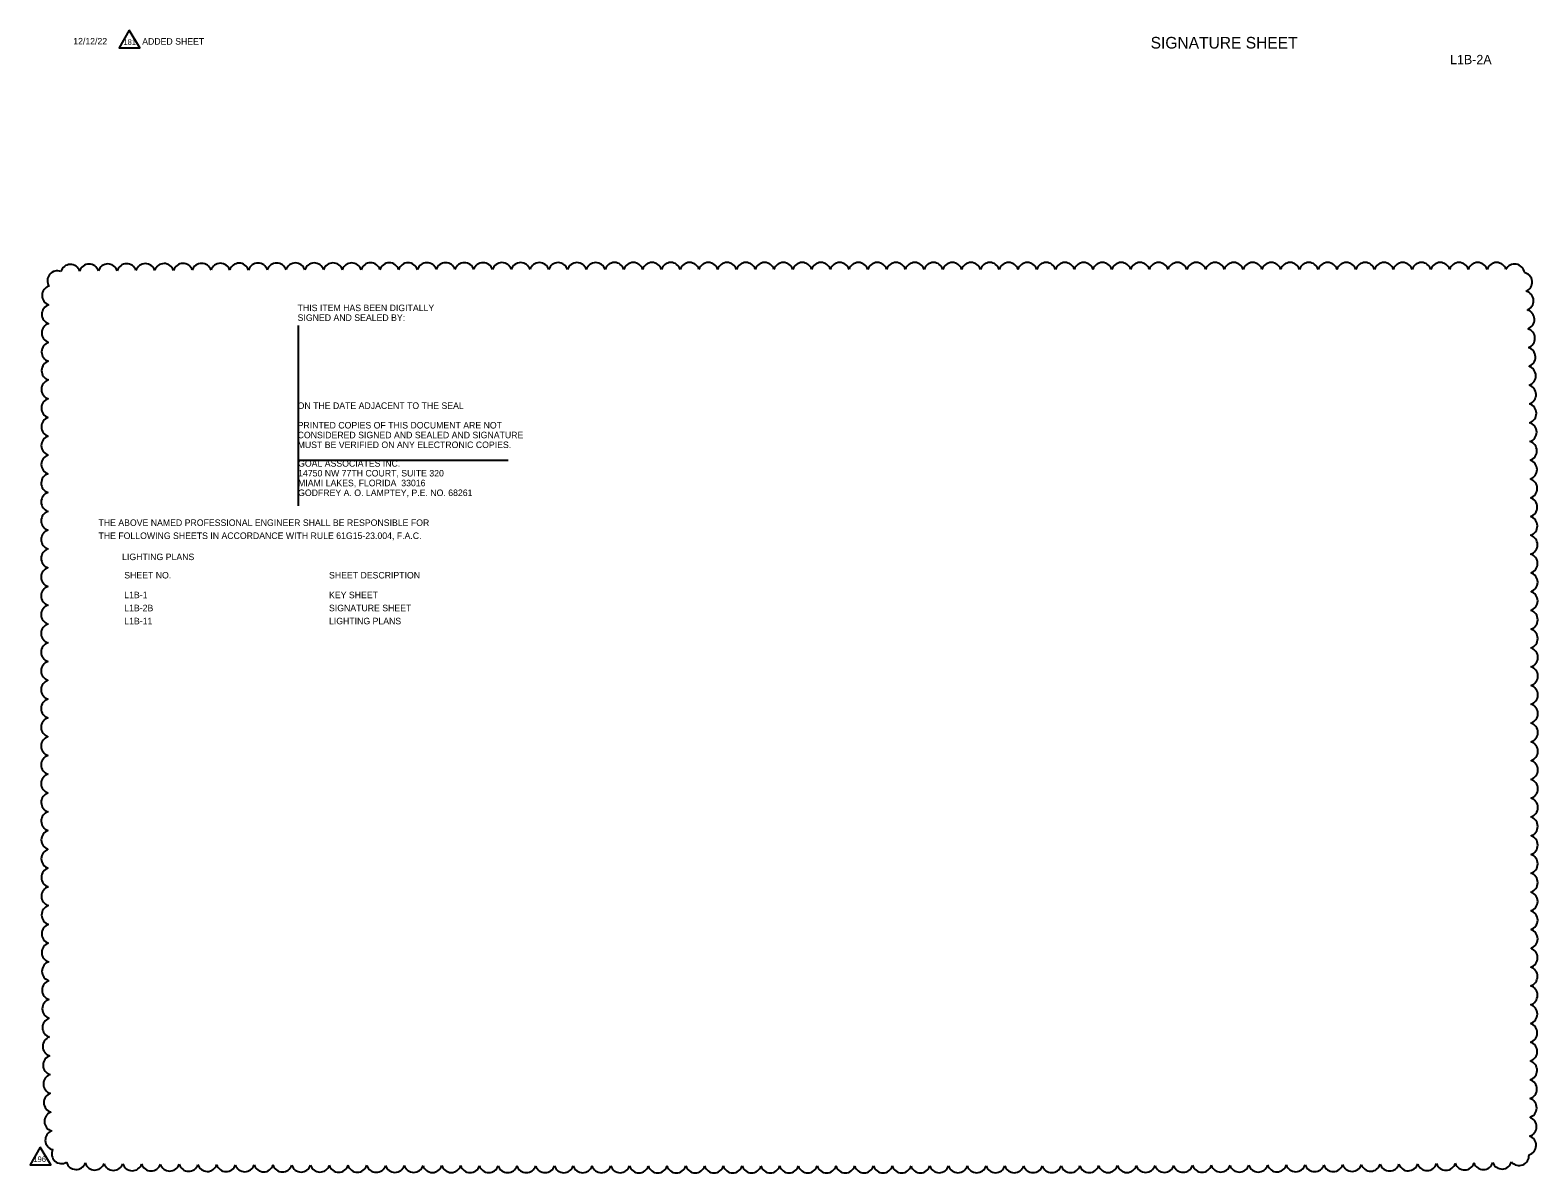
# Model space of a CAD drawing. Extents: x -811.2 to -755.6, y -2295.2 to -2235.1.
# Drawn here: x -811.23 to -795.04, y -2269.67 to -2257.4 of the extents above; entities that cross this region are included whole.
import ezdxf

# ---------------------------------------------------------------- set-up
doc = ezdxf.new("R2010")
doc.units = 0
for name, color, linetype in [('Cloud_dp', 7, 'Continuous'), ('ScratchEle_dp', 7, 'Continuous'), ('TextMinor', 7, 'Continuous'), ('TextMisc', 7, 'Continuous'), ('TextNotes', 7, 'Continuous'), ('TextShtNo', 7, 'Continuous')]:
    doc.layers.add(name, color=color, linetype=linetype)

msp = doc.modelspace()

# ---------------------------------------------------------------- linework, layer by layer
at = {"layer": 'Cloud_dp'}
for points in [[(-810.168, -2257.402), (-810.276, -2257.59), (-810.055, -2257.59)], [(-811.125, -2269.395), (-811.233, -2269.584), (-811.012, -2269.584)]]:
    msp.add_lwpolyline(points, close=True, dxfattribs=at)
for centre, start, end in [((-810.801, -2260.023), 18.5945, 163.5945), ((-810.6, -2260.019), 18.2142, 163.2142), ((-810.398, -2260.017), 18.047, 163.047), ((-810.197, -2260.015), 17.9467, 162.9467), ((-809.995, -2260.014), 17.8779, 162.8779), ((-809.794, -2260.013), 17.8269, 162.8269), ((-809.592, -2260.012), 17.7872, 162.7872), ((-809.391, -2260.011), 17.7551, 162.7551), ((-809.189, -2260.01), 17.7284, 162.7284), ((-808.988, -2260.009), 17.7058, 162.7058), ((-808.786, -2260.008), 17.6864, 162.6864), ((-808.585, -2260.008), 17.6694, 162.6694), ((-808.383, -2260.007), 17.6544, 162.6544), ((-808.182, -2260.007), 17.6411, 162.6411), ((-807.98, -2260.006), 17.629, 162.629), ((-807.779, -2260.006), 17.6182, 162.6182), ((-807.577, -2260.005), 17.6083, 162.6083), ((-807.376, -2260.005), 17.5992, 162.5992), ((-807.174, -2260.005), 17.5908, 162.5908), ((-806.972, -2260.004), 17.5831, 162.5831), ((-806.771, -2260.004), 17.576, 162.576), ((-806.569, -2260.004), 17.5693, 162.5693), ((-806.368, -2260.004), 17.563, 162.563), ((-806.166, -2260.003), 17.5572, 162.5572), ((-805.965, -2260.003), 17.5517, 162.5517), ((-805.763, -2260.003), 17.5465, 162.5465), ((-805.562, -2260.003), 17.5417, 162.5417), ((-805.36, -2260.003), 17.537, 162.537), ((-805.159, -2260.003), 17.5327, 162.5327), ((-804.957, -2260.002), 17.5285, 162.5285), ((-804.755, -2260.002), 17.5246, 162.5246), ((-804.554, -2260.002), 17.5208, 162.5208), ((-804.352, -2260.002), 17.5172, 162.5172), ((-804.151, -2260.002), 17.5137, 162.5137), ((-803.949, -2260.002), 17.5105, 162.5105), ((-803.748, -2260.002), 17.5073, 162.5073), ((-803.546, -2260.002), 17.5043, 162.5043), ((-803.345, -2260.002), 17.5014, 162.5014), ((-803.143, -2260.002), 17.5, 162.5), ((-802.941, -2260.002), 17.5, 162.5), ((-802.74, -2260.002), 17.5, 162.5), ((-802.538, -2260.002), 17.5, 162.5), ((-802.337, -2260.002), 17.5, 162.5), ((-802.135, -2260.002), 17.5, 162.5), ((-801.934, -2260.002), 17.5, 162.5), ((-801.732, -2260.002), 17.5, 162.5), ((-801.531, -2260.002), 17.5, 162.5), ((-801.329, -2260.002), 17.5, 162.5), ((-801.128, -2260.002), 17.5, 162.5), ((-800.926, -2260.002), 17.5, 162.5), ((-800.724, -2260.002), 17.5, 162.5), ((-800.523, -2260.002), 17.5, 162.5), ((-800.321, -2260.002), 17.5, 162.5), ((-800.12, -2260.002), 17.5, 162.5), ((-799.918, -2260.002), 17.5, 162.5), ((-799.717, -2260.002), 17.5, 162.5), ((-799.515, -2260.002), 17.5, 162.5), ((-799.314, -2260.002), 17.5, 162.5), ((-799.112, -2260.002), 17.5, 162.5), ((-798.911, -2260.002), 17.5, 162.5), ((-798.709, -2260.002), 17.5, 162.5), ((-798.507, -2260.002), 17.5, 162.5), ((-798.306, -2260.002), 17.5, 162.5), ((-798.104, -2260.002), 17.5, 162.5), ((-797.903, -2260.002), 17.5, 162.5), ((-797.701, -2260.002), 17.5, 162.5), ((-797.5, -2260.002), 17.5, 162.5), ((-797.298, -2260.002), 17.5, 162.5), ((-797.097, -2260.002), 17.5, 162.5), ((-796.895, -2260.002), 17.5, 162.5), ((-796.693, -2260.002), 17.5, 162.5), ((-796.492, -2260.002), 17.5, 162.5), ((-796.29, -2260.002), 17.5, 162.5), ((-796.089, -2260.002), 17.5, 162.5), ((-795.887, -2260.002), 17.5, 162.5), ((-795.686, -2260.002), 17.5, 162.5), ((-795.484, -2260.002), 17.5, 162.5), ((-795.29, -2260.019), 7.7061, 152.7061), ((-810.941, -2260.091), 68.4395, 213.4395), ((-795.207, -2260.108), 293.1451, 78.1451), ((-810.999, -2260.25), 106.8045, 251.8045), ((-795.192, -2260.307), 290.3535, 75.3535), ((-811.001, -2260.452), 107.0437, 252.0437), ((-795.183, -2260.508), 289.5186, 74.5186), ((-811.002, -2260.653), 107.1562, 252.1562), ((-795.177, -2260.71), 289.0656, 74.0656), ((-811.004, -2260.855), 107.2253, 252.2253), ((-795.172, -2260.911), 288.7699, 73.7699), ((-811.004, -2261.056), 107.2734, 252.2734), ((-795.168, -2261.112), 288.5573, 73.5573), ((-811.005, -2261.258), 107.3093, 252.3093), ((-795.165, -2261.314), 288.3949, 73.3949), ((-811.006, -2261.459), 107.3374, 252.3374), ((-795.162, -2261.515), 288.2656, 73.2656), ((-811.006, -2261.661), 107.3603, 252.3603), ((-795.159, -2261.717), 288.1595, 73.1595), ((-811.007, -2261.862), 107.3793, 252.3793), ((-795.157, -2261.918), 288.0704, 73.0704), ((-811.007, -2262.064), 107.3954, 252.3954), ((-795.155, -2262.12), 287.9942, 72.9942), ((-811.008, -2262.265), 107.4094, 252.4094), ((-795.153, -2262.321), 287.928, 72.928), ((-811.008, -2262.467), 107.4216, 252.4216), ((-795.152, -2262.523), 287.8698, 72.8698), ((-811.008, -2262.669), 107.4323, 252.4323), ((-795.151, -2262.724), 287.8182, 72.8182), ((-811.008, -2262.87), 107.442, 252.442), ((-795.15, -2262.926), 287.772, 72.772), ((-811.008, -2263.072), 107.4506, 252.4506), ((-795.149, -2263.127), 287.7302, 72.7302), ((-811.009, -2263.273), 107.4585, 252.4585), ((-795.148, -2263.329), 287.6923, 72.6923), ((-811.009, -2263.475), 107.4656, 252.4656), ((-795.148, -2263.53), 287.6577, 72.6577), ((-811.009, -2263.676), 107.4722, 252.4722), ((-795.147, -2263.732), 287.6259, 72.6259), ((-811.009, -2263.878), 107.4782, 252.4782), ((-795.147, -2263.933), 287.5965, 72.5965), ((-811.009, -2264.079), 107.4838, 252.4838), ((-795.146, -2264.135), 287.5693, 72.5693), ((-811.009, -2264.281), 107.489, 252.489), ((-795.146, -2264.336), 287.544, 72.544), ((-811.009, -2264.482), 107.4938, 252.4938), ((-795.146, -2264.538), 287.5204, 72.5204), ((-811.009, -2264.684), 107.4984, 252.4984), ((-795.146, -2264.739), 287.5008, 72.5008), ((-811.009, -2264.886), 107.5115, 252.5115), ((-795.146, -2264.941), 287.4924, 72.4924), ((-811.009, -2265.087), 107.531, 252.531), ((-795.146, -2265.143), 287.4849, 72.4849), ((-811.009, -2265.289), 107.5519, 252.5519), ((-795.146, -2265.344), 287.4769, 72.4769), ((-811.009, -2265.49), 107.5743, 252.5743), ((-795.146, -2265.546), 287.4682, 72.4682), ((-811.008, -2265.692), 107.5985, 252.5985), ((-795.146, -2265.747), 287.4589, 72.4589), ((-811.008, -2265.893), 107.6247, 252.6247), ((-795.147, -2265.949), 287.4488, 72.4488), ((-811.007, -2266.095), 107.6531, 252.6531), ((-795.147, -2266.15), 287.4378, 72.4378), ((-811.007, -2266.296), 107.6841, 252.6841), ((-795.147, -2266.352), 287.4258, 72.4258), ((-811.006, -2266.498), 107.7182, 252.7182), ((-811.005, -2266.699), 107.7558, 252.7558), ((-795.147, -2266.553), 287.4126, 72.4126), ((-795.148, -2266.755), 287.398, 72.398), ((-811.004, -2266.901), 107.7976, 252.7976), ((-795.148, -2266.956), 287.3817, 72.3817), ((-811.003, -2267.102), 107.8445, 252.8445), ((-795.148, -2267.158), 287.3633, 72.3633), ((-811.002, -2267.304), 107.8977, 252.8977), ((-811, -2267.505), 107.9585, 252.9585), ((-795.149, -2267.359), 287.3425, 72.3425), ((-795.15, -2267.561), 287.3185, 72.3185), ((-810.999, -2267.707), 108.0291, 253.0291), ((-795.15, -2267.763), 287.2905, 72.2905), ((-810.997, -2267.908), 108.1124, 253.1124), ((-795.151, -2267.964), 287.2573, 72.2573), ((-810.994, -2268.11), 108.2128, 253.2128), ((-810.992, -2268.311), 108.3369, 253.3369), ((-795.152, -2268.166), 287.217, 72.217), ((-795.153, -2268.367), 287.1666, 72.1666), ((-810.988, -2268.513), 108.4961, 253.4961), ((-795.154, -2268.569), 287.101, 72.101), ((-810.985, -2268.714), 108.7107, 253.7107), ((-795.156, -2268.77), 287.0106, 72.0106), ((-810.98, -2268.915), 109.023, 254.023), ((-810.973, -2269.117), 109.542, 254.542), ((-795.158, -2268.972), 286.8744, 71.8744), ((-795.16, -2269.173), 286.6317, 71.6317), ((-810.964, -2269.317), 110.7101, 255.7101), ((-795.165, -2269.374), 285.9387, 70.9387), ((-810.895, -2269.464), 155.0652, 300.0652), ((-795.241, -2269.484), 219.2472, 4.2472), ((-810.74, -2269.527), 195.6294, 340.6294), ((-810.539, -2269.533), 196.2647, 341.2647), ((-810.337, -2269.537), 196.5499, 341.5499), ((-810.136, -2269.54), 196.722, 341.722), ((-809.934, -2269.542), 196.8406, 341.8406), ((-809.733, -2269.544), 196.9286, 341.9286), ((-809.531, -2269.546), 196.9974, 341.9974), ((-809.33, -2269.548), 197.053, 342.053), ((-809.128, -2269.549), 197.0992, 342.0992), ((-808.927, -2269.551), 197.1383, 342.1383), ((-808.725, -2269.552), 197.1721, 342.1721), ((-808.524, -2269.553), 197.2016, 342.2016), ((-808.322, -2269.554), 197.2276, 342.2276), ((-808.121, -2269.555), 197.2509, 342.2509), ((-807.919, -2269.556), 197.2717, 342.2717), ((-807.718, -2269.556), 197.2907, 342.2907), ((-807.516, -2269.557), 197.3079, 342.3079), ((-807.315, -2269.558), 197.3237, 342.3237), ((-807.113, -2269.558), 197.3382, 342.3382), ((-806.912, -2269.559), 197.3516, 342.3516), ((-806.71, -2269.559), 197.3641, 342.3641), ((-806.508, -2269.56), 197.3757, 342.3757), ((-806.307, -2269.56), 197.3866, 342.3866), ((-806.105, -2269.561), 197.3967, 342.3967), ((-805.904, -2269.561), 197.4063, 342.4063), ((-805.702, -2269.561), 197.4153, 342.4153), ((-805.501, -2269.562), 197.4238, 342.4238), ((-805.299, -2269.562), 197.4318, 342.4318), ((-805.098, -2269.562), 197.4395, 342.4395), ((-804.896, -2269.562), 197.4467, 342.4467), ((-804.695, -2269.563), 197.4536, 342.4536), ((-804.493, -2269.563), 197.4602, 342.4602), ((-804.292, -2269.563), 197.4664, 342.4664), ((-804.09, -2269.563), 197.4724, 342.4724), ((-803.888, -2269.563), 197.4782, 342.4782), ((-803.687, -2269.563), 197.4837, 342.4837), ((-803.485, -2269.563), 197.4889, 342.4889), ((-803.284, -2269.563), 197.494, 342.494), ((-803.082, -2269.563), 197.4989, 342.4989), ((-802.881, -2269.563), 197.5044, 342.5044), ((-802.679, -2269.563), 197.5105, 342.5105), ((-802.478, -2269.563), 197.5167, 342.5167), ((-802.276, -2269.563), 197.5233, 342.5233), ((-802.074, -2269.563), 197.5301, 342.5301), ((-801.873, -2269.563), 197.5372, 342.5372), ((-801.671, -2269.563), 197.5447, 342.5447), ((-801.47, -2269.562), 197.5525, 342.5525), ((-801.268, -2269.562), 197.5607, 342.5607), ((-801.067, -2269.562), 197.5693, 342.5693), ((-800.865, -2269.562), 197.5784, 342.5784), ((-800.664, -2269.562), 197.5879, 342.5879), ((-800.462, -2269.561), 197.598, 342.598), ((-800.261, -2269.561), 197.6087, 342.6087), ((-800.059, -2269.56), 197.62, 342.62), ((-799.858, -2269.56), 197.6321, 342.6321), ((-799.656, -2269.559), 197.6449, 342.6449), ((-799.454, -2269.559), 197.6587, 342.6587), ((-799.253, -2269.558), 197.6734, 342.6734), ((-799.051, -2269.558), 197.6893, 342.6893), ((-798.85, -2269.557), 197.7064, 342.7064), ((-798.648, -2269.556), 197.725, 342.725), ((-798.447, -2269.555), 197.7453, 342.7453), ((-798.245, -2269.555), 197.7675, 342.7675), ((-798.044, -2269.554), 197.792, 342.792), ((-797.842, -2269.552), 197.8192, 342.8192), ((-797.641, -2269.551), 197.8496, 342.8496), ((-797.439, -2269.55), 197.8839, 342.8839), ((-797.238, -2269.549), 197.9231, 342.9231), ((-797.036, -2269.547), 197.9684, 342.9684), ((-796.835, -2269.545), 198.0216, 343.0216), ((-796.633, -2269.543), 198.0853, 343.0853), ((-796.432, -2269.541), 198.1633, 343.1633), ((-796.23, -2269.539), 198.2623, 343.2623), ((-796.029, -2269.536), 198.3936, 343.3936), ((-795.827, -2269.532), 198.5799, 343.5799), ((-795.626, -2269.528), 198.8753, 343.8753), ((-795.425, -2269.522), 199.4643, 344.4643)]:
    msp.add_arc(centre, 0.106, start, end, dxfattribs=at)
at = {"layer": 'ScratchEle_dp'}
for p, q in [((-808.355, -2260.573), (-808.355, -2262.508)), ((-808.355, -2262.018), (-806.098, -2262.018))]:
    msp.add_line(p, q, dxfattribs=at)

# ---------------------------------------------------------------- texts
at = {"layer": 'Cloud_dp'}
for s, p in [('181', (-810.23, -2257.56)), ('196', (-811.197, -2269.553))]:
    msp.add_text(s, height=0.06, rotation=0, dxfattribs=at).set_placement(p)
at = {"layer": 'TextMinor'}
for s, p in [('12/12/22', (-810.77, -2257.555)), ('ADDED SHEET', (-810.029, -2257.557))]:
    msp.add_text(s, height=0.07, dxfattribs=at).set_placement(p)
at = {"layer": 'TextMisc'}
for s, height, p in [('       SIGNATURE SHEET         ', 0.125, (-799.524, -2257.599)), ('THIS ITEM HAS BEEN DIGITALLY', 0.07, (-808.36, -2260.418)), ('SIGNED AND SEALED BY:', 0.07, (-808.36, -2260.523)), ('ON THE DATE ADJACENT TO THE SEAL', 0.07, (-808.36, -2261.468)), ('CONSIDERED SIGNED AND SEALED AND SIGNATURE ', 0.07, (-808.36, -2261.783)), ('PRINTED COPIES OF THIS DOCUMENT ARE NOT ', 0.07, (-808.36, -2261.678)), ('MUST BE VERIFIED ON ANY ELECTRONIC COPIES.', 0.07, (-808.36, -2261.888)), ('GOAL ASSOCIATES INC.', 0.07, (-808.355, -2262.088)), ('14750 NW 77TH COURT, SUITE 320', 0.07, (-808.355, -2262.193)), ('MIAMI LAKES, FLORIDA  33016', 0.07, (-808.355, -2262.298)), ('GODFREY A. O. LAMPTEY, P.E. NO. 68261', 0.07, (-808.355, -2262.403)), ('THE ABOVE NAMED PROFESSIONAL ENGINEER SHALL BE RESPONSIBLE FOR ', 0.07, (-810.499, -2262.724)), ('THE FOLLOWING SHEETS IN ACCORDANCE WITH RULE 61G15-23.004, F.A.C.', 0.07, (-810.499, -2262.864)), ('LIGHTING PLANS', 0.07, (-810.245, -2263.091))]:
    msp.add_text(s, height=height, dxfattribs=at).set_placement(p)
at = {"layer": 'TextNotes'}
for s, p in [('SHEET NO.', (-810.222, -2263.288)), ('SHEET DESCRIPTION', (-808.023, -2263.288)), ('L1B-1', (-810.222, -2263.5)), ('KEY SHEET', (-808.023, -2263.5)), ('L1B-2B', (-810.222, -2263.64)), ('SIGNATURE SHEET', (-808.023, -2263.64)), ('L1B-11', (-810.222, -2263.78)), ('LIGHTING PLANS', (-808.023, -2263.78))]:
    msp.add_text(s, height=0.07, dxfattribs=at).set_placement(p)
at = {"layer": 'TextShtNo'}
msp.add_text('L1B-2A ', height=0.1, dxfattribs=at).set_placement((-795.983, -2257.767))

doc.saveas('drawing.dxf')
